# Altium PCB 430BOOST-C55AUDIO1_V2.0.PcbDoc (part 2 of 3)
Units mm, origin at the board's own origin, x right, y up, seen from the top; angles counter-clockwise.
Board outline 50.8 x 84 mm, 4 copper layers (Top Layer, GND, POW, Bottom Layer); 272 components, 169 nets, 833 pads, 607 vias.
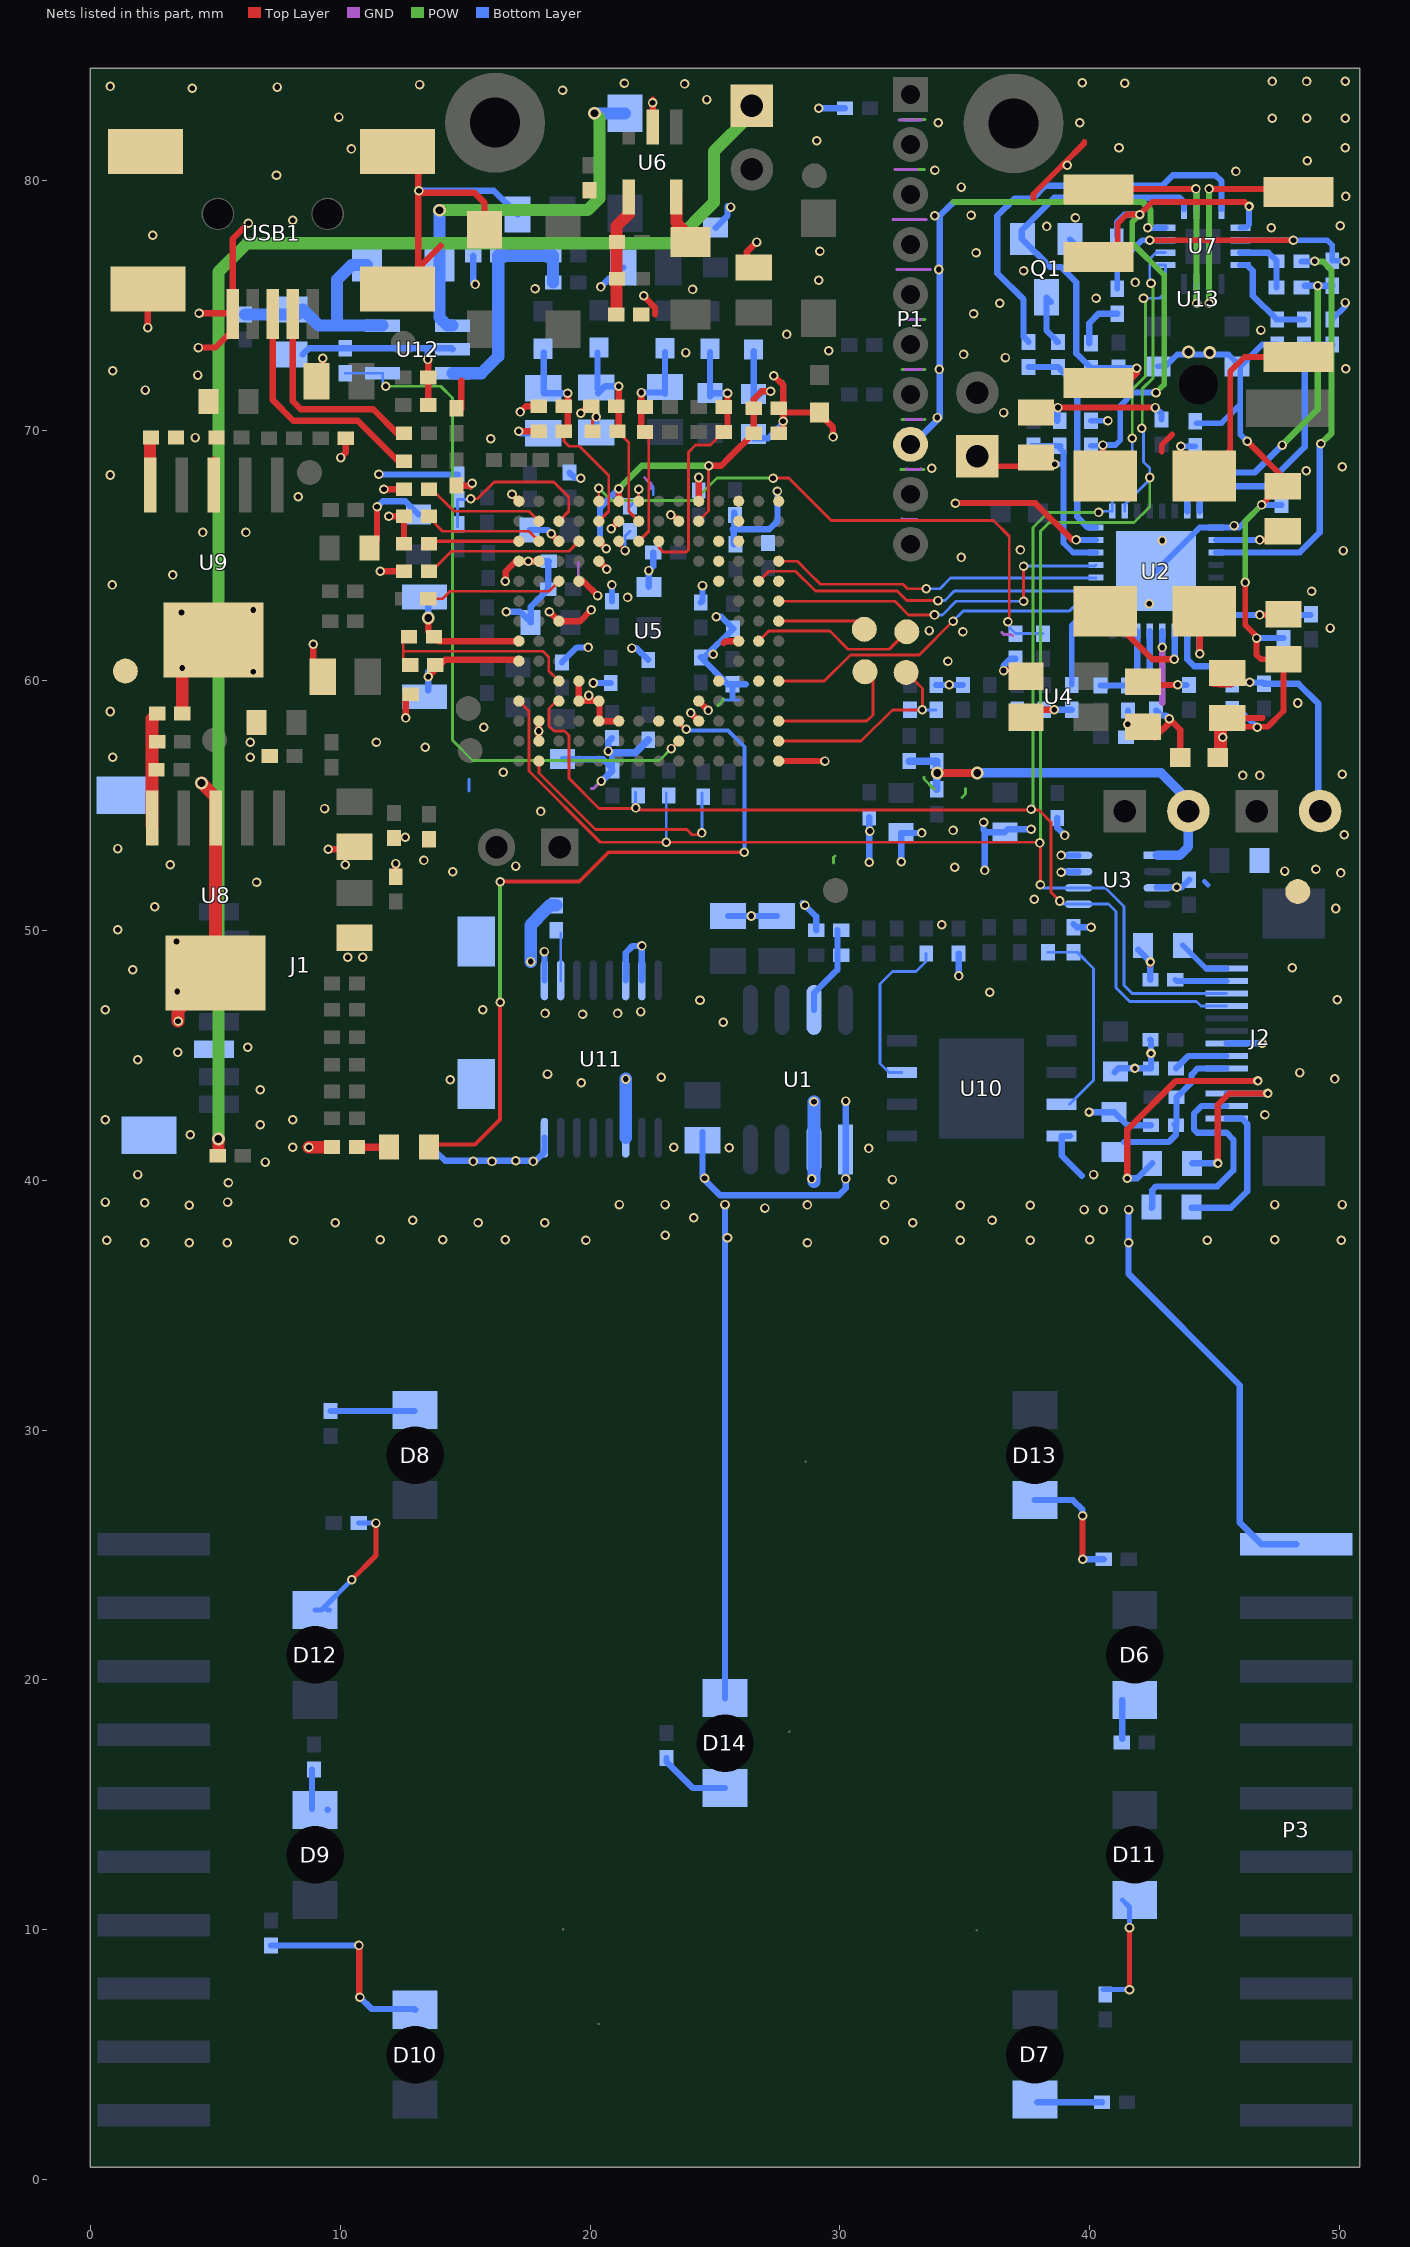
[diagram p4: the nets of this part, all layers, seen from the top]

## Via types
v1: diameter 0.381, hole 0.229, Top Layer to Bottom Layer, 549 vias
v2: diameter 0.508, hole 0.305, Top Layer to Bottom Layer, 42 vias
v3: diameter 0.381, hole 0.203, Top Layer to Bottom Layer, 16 vias

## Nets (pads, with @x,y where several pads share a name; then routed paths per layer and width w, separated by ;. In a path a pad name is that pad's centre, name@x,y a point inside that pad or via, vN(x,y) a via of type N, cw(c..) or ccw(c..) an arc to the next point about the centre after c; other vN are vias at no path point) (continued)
GND: C1.2 C4.1 C6.2 C8.1 C11.1 C14.1 C18.2 C19.1 C20.1 C21.2 C22.2 C25.1 C26.1 C27.1 C32.1 C33.1 C34.1 C35.1 C36.1 C37.1 C38.1 C39.1 C43.1 C44.1 C45.1 C46.1 C47.1 C48.1 C49.1 C50.1 C51.1 C52.1 C53.1 C54.1 C55.1 C56.2 C57.1 C58.1 C62.2 C63.1 C64.1 C65.1 C66.1 C67.1 C68.1 C73.2 C74.2 C75.1 C76.2 C77.2 C78.2 C80.1 C81.1 C82.1 C83.1 C85.2 C87.1 C88.1 C89.1 C100.2 C101.2 C102.2 C104.1 C105.2 C107.1 C108.1 C200.1 C201.1 C202.1 C203.1 C206.2 C210.1 C211.1 C220.1 D2.1 D14.2 J1.6 J1.9 J1.10 J1.11 J1.12 J2.7 L2.1 L8.1 P1.8 P3.1 R5.1 R6.1 R13.1 R16.1 R24.2 R25.1 R28.1 R29.1 R30.1 R32.1 R35.1 R40.1 R42.1 R45.2 R46.2 R47.2 R50.1 R52.1 R54.2 R56.1 R75.1 R77.2 R81.1 R82.1 R97.2 TP1.1 TP4.1 U1.1 U1.2 U2.7 U2.28 U3.3 U3.7 U3.8 U4.2 U5.A11 U5.A14 U5.B2 U5.B3 U5.B11 U5.C8 U5.C12 U5.D4 U5.D5 U5.D10 U5.E3 U5.E4 U5.E11 U5.F3 U5.F13 U5.H3 U5.J13 U5.K3 U5.K4 U5.K14 U5.L5 U5.L10 U5.M7 U5.P1 U5.P14 U6.2 U7.4 U8.3 U9.3 U10.4 U11.3 U11.8 U11.9 U11.14 U11.15 U12.2 USB1.5 USB1.6 USB1.7 USB1.8 USB1.9 | length 298.7
  Top Layer w0.114: C57.1@20.1,69.975 20.1,70.4 v1(20.25,70.55)
  Top Layer w0.25: v1(2.3,74.125) USB1.8@2.3,75.675 ; v1(4.325,73.325) 5,73.325 5.7,74.025 USB1.5@5.7,74.675 ; v1(4.35,74.7) 5.675,74.7 USB1.5@5.7,74.675 ; U9.3@4.935,67.825 U9.3@4.935,68.84 ; v1(6.325,78.305) 5.7,77.68 USB1.5@5.7,74.675 ; C21.2@8.825,71.625 C21.2@8.825,72.275 ; C21.2@8.9,71.975 C21.2@8.9,72.5 ; v1(8.925,61.45) 8.925,60.525 C85.2@9.3,60.15 ; C21.2@9.05,71.975 9.3,72.225 v1(9.3,72.9) ; v1(9.525,53.25) C62.2@10.575,53.25 ; v1(10.025,68.925) 10.225,69.125 R56.1@10.225,69.7 ; C89.1@11.175,65.3 11.475,65.6 v1(11.475,66.95) ; v1(11.6,64.375) R28.1@12.55,64.375 ; v1(11.75,67.65) R47.2@12.55,67.65 ; v1(11.95,66.575) R46.2@12.55,66.575 R45.2@12.55,65.475 ; v1@16.625,62.775 v1(16.65,62.75) ; v1(17.15,69.975) C19.1@17.95,69.975 ; v1(17.2,70.75) 17.425,70.975 C20.1@17.95,70.975 ; v1(18.45,65.875) U5.C12@18.75,65.575 ; v1(19.625,70.7) 19.9,70.975 C58.1@20.05,70.975 ; v1(19.925,61.325) v1@19.975,61.375 ; U5.E11@20.463,64.662 v1@20.7,64.425 ; U5.P1@27.55,56.775 v1(29.4,56.775) ; C44.1@27.55,70.9 27.724,70.726 L8.1@29.175,70.726 29.175,70.675 29.725,70.125 v1(29.725,69.75) ; v1(34.625,67.1) 37.825,67.1 v1@39.3,65.625 ; v1(36.55,60.4) 37.225,60.4 U4.2@37.45,60.175 ; C6.2@37.525,70.725 C6.2@37.525,71.05 ; C6.2@38.201,70.925 v1(38.725,70.925) v1(42.625,70.925) v1@42.65,70.95 ; v1(41.525,58.25) 42.075,58.25 42.6,57.725 43.175,58.3 v1(43.175,58.475) 43.626,58.024 L2.1@43.626,56.925
  Top Layer w0.254: USB1.9@0.975,80.525 1.625,81.175 USB1.9@2.2,81.175 ; C201.1@12.225,52.075 v1(12.225,52.675) ; USB1.6@12.3,75.675 USB1.6@13.125,76.5 ; USB1.7@12.3,81.175 13.125,80.35 13.125,79.6 v1@13.125,79.525 ; v1(12.625,58.5) R35.1@12.625,59.45 ; v1(13.5,72.85) 13.525,72.825 R25.1@13.525,72.125 13.525,71.575 C22.2@13.525,71.025 ; 14.025,77.4 USB1.6@13.125,76.5 ; C11.1@14.65,67.8 15.2,67.8 v1@15.225,67.775 ; C107.1@14.85,70.85 14.85,72 ; D2.1@15.775,78.05 15.775,79.125 15.375,79.525 v1@13.125,79.525 ; v1(16.601,63.978) 16.625,64.002 16.625,64.375 17.025,64.775 U5.A11@17.15,64.775 17.376,64.775 v1(17.525,64.775) U5.B11@17.95,64.775 ; U5.A14@17.15,67.175 v1@16.961,67.364 ; U5.B2@17.95,57.575 v1(17.95,57.975) U5.B3@17.95,58.375 ; v1(18.375,62.75) U5.C8@18.75,62.375 19.6,62.375 v1(20.05,62.825) ; U5.D5@19.55,59.975 U5.D4@19.55,59.175 19.557,59.182 20.001,59.182 ; U5.D10@19.55,63.975 19.725,63.975 v1(20.3,63.4) ; v1@20.001,59.324 20.001,59.182 ; v1(20.85,66.075) U5.F13@21.15,66.375 ; U5.F3@21.15,58.375 U5.E3@20.35,58.375 20.38,58.405 20.38,59.145 20.343,59.182 20.001,59.182 ; v1@22.225,75.3 22.6,74.925 22.6,74.65 ; U6.2@22.513,82.15 v1@22.513,83.237 ; v1@23.225,66.7 U5.J13@23.55,66.375 ; v1(24.025,58.7) U5.K3@24.35,58.375 ; U5.K4@24.35,59.175 v1(24.725,58.8) ; U5.K14@24.35,67.175 v1(24.35,68.125) ; 25.35,61.503 25.422,61.575 U5.M7@25.95,61.575 ; C74.2@26.275,76.525 26.275,77.15 v1(26.675,77.55) ; v1(27.35,72.2) 27.725,71.825 v1@27.725,70.553 ; C45.1@27.55,69.9 C45.1@27.657,70.007 ; C45.1@27.725,70 v1@27.725,70.553 ; v1(27.725,70.375) v1@27.725,70.553 ; v3@39.95,42.7 v3(39.975,42.725) ; v3@41.8,44.475 v3(41.802,44.475) ; v3@42.425,48.65 v3(42.425,48.741) ; v3(46.9,45.475) v3@46.925,45.45 ; USB1.6@13.125,76.5 v1@13.125,79.525 ; v1@16.961,67.364 v1(16.875,67.45) v1@16.961,67.364
  Top Layer w0.508: v1(3.51,46.365) 3.51,46.8 U8.3@5.01,48.3 U8.3@5.01,54.5 5.01,55.34 v2(4.45,55.9) ; R54.2@3.675,58.675 U9.3@3.675,60.365 ; v1(8.75,41.325) R40.1@9.575,41.325
  GND w0.114: 19.525,64.059 19.525,64.73 ; 20.064,55.673 20.142,55.673 v1(20.445,55.976) ; 22.183,68.125 22.451,67.856 22.451,67.675 ; 32.127,78.454 33.102,78.454 33.47,78.454 ; 32.2,80.45 33.075,80.45 ; 32.277,76.454 33.62,76.454 ; 32.364,82.439 33.277,82.439 ; 32.475,66.475 32.5,66.45 33.075,66.45 ; 32.584,74.45 33.255,74.45 ; 32.609,72.45 33.28,72.45 ; 32.634,70.45 33.305,70.45 ; 32.657,68.475 32.682,68.45 33.225,68.45 33.25,68.475 ; 36.475,61.925 36.554,61.846 36.859,61.846 36.927,61.778
  GND w0.254: 42.9,59.1 v1(42.9,61.325)
  POW w0.114: 25.109,58.988 25.325,59.205 25.325,59.275 ; 27.719,71.486 27.719,71.975 ; 29.749,52.702 29.749,52.924 29.801,52.976 ; 32.434,68.45 33.359,68.45 ; 32.459,78.45 33.384,78.45 ; 32.459,80.45 33.384,80.45 ; 32.484,70.45 33.409,70.45 ; 32.484,72.45 33.409,72.45 ; 32.484,74.45 33.409,74.45 ; 32.484,82.45 33.409,82.45 ; 32.509,76.45 33.434,76.45 ; 33.361,56.131 33.361,56.064 33.775,55.65 ; 34.888,55.313 35.026,55.451 35.026,55.673
  POW w0.254: v1@20.419,55.95 v1(20.445,55.976) ; 34.55,79.15 42.111,79.15 42.432,78.829 42.432,78.232 v1(42.325,78.125)
  Bottom Layer w0.114: 15.15,56.05 15.161,56.039 15.161,55.577 ; 20.064,55.673 20.142,55.673 v1(20.445,55.976) ; 22.275,68 22.501,67.774 ; 22.526,67.446 22.526,67.724 ; 25.225,59.125 25.314,59.214 25.954,59.214 ; 32.5,80.45 33.075,80.45 ; 32.525,78.45 33.1,78.45 ; 32.55,76.45 33.125,76.45 ; 32.55,82.439 33.136,82.439 ; 32.65,70.45 33.225,70.45 ; 32.65,76.45 33.225,76.45 ; 32.65,78.45 33.225,78.45 ; 32.675,74.45 33.25,74.45
  Bottom Layer w0.2: 44.6,51.95 44.725,51.825
  Bottom Layer w0.25: C102.2@8.5,73.05 8.75,73.3 R82.1@10.2,73.3 13.5,73.3 ; v1(11.475,66.95) 11.7,67.175 12.6,67.175 C82.1@13.125,66.65 ; v1(11.55,68.25) R42.1@14.7,68.25 ; v1(13.5,72.85) 13.5,73.3 ; U12.2@14.5,73.263 14.463,73.3 13.5,73.3 ; v1(16.65,62.75) 17.2,62.75 C35.1@17.625,62.325 17.625,62.95 C53.1@18.325,63.65 C33.1@18.325,64.75 ; v1(17.15,69.975) 17.225,69.9 C18.2@18.125,69.9 ; v1(17.525,64.775) C33.1@18.35,64.775 ; C37.1@17.575,66.025 18.3,66.025 v1(18.45,65.875) ; C27.1@18.875,60.725 19.475,61.325 v1(19.925,61.325) ; C32.1@19.175,68.325 19.4,68.1 v1(19.625,68.1) ; C56.2@20.25,69.925 v1(20.25,70.55) v1@20.25,70.7 ; v1(20.425,75.75) 21.2,76.525 C105.2@21.325,76.525 ; C55.1@20.875,63.175 v1(20.875,63.825) ; C54.1@22.35,63.75 v1(22.35,64.4) 22.525,64.575 C48.1@22.525,65.125 ; D14.2@25.4,19.27 25.4,21.5 ; 25.4,20.54 25.4,21.5 ; 25.4,35.375 25.4,33.2 ; v1(25.4,39.025) 25.4,33.2 ; C77.2@25.525,50.575 v1(26.45,50.575) C78.2@27.475,50.575 ; C43.1@26.55,69.7 27.125,69.7 27.625,70.2 ; v1@28.5,51.1 29.05,50.55 R52.1@29.05,50 ; v1(29.15,82.9) R6.1@30.2,82.9 ; v1(31.175,52.725) C50.1@31.175,54.525 ; v1(32.45,52.75) C39.1@32.45,53.9 v1(33.275,53.9) ; R97.2@33.85,59.825 v1(34.375,59.825) R32.1@34.925,59.825 ; v1(35.75,54.325) 35.75,54.025 35.85,53.925 ; v1(35.8,52.4) 35.8,53.875 35.85,53.925 ; v1(36.55,60.4) 36.55,60.6 36.825,60.875 R29.1@37.025,60.875 ; v1(37.65,54.05) 36.725,54.05 C52.1@36.6,53.925 ; C34.1@38.7,54.5 38.7,54.1 v1(39,53.8) ; C8.1@38.7,70.4 v1@38.7,70.925 ; v1@38.825,52.35 U3.7@39.55,52.35 ; v1@38.825,53 U3.8@39.55,53 ; R75.1@39.35,50.25 39.475,50.125 v1(40.05,50.125) ; C14.1@41.525,57.8 v1(41.525,58.25) R24.2@41.525,58.8 ; v1(42.625,70.925) 42.875,70.675 R16.1@42.875,70.45 ; C4.1@42.65,58.8 42.85,58.6 43.05,58.6 v1(43.175,58.475) ; U3.3@42.675,51.725 v1@43.45,51.725 ; 25.4,21.5 25.4,33.2 ; 35.85,53.925 C52.1@36.6,53.925 ; 35.85,53.925 C52.1@36.6,53.925
  Bottom Layer w0.254: v1(13.15,79.6) 16.15,79.6 C73.2@17.1,78.65 ; 13.85,41.125 14.2,40.775 v1(17.025,40.775) 17.825,40.775 18.175,41.125 U11.8@18.175,41.7 18.175,41.175 U11.8@18.125,41.125 ; R81.1@15.325,77 15.325,75.925 v1(15.4,75.85) ; U11.9@18.175,48 v1(18.175,49.15) ; C26.1@18.9,56.85 20.525,56.85 20.875,56.5 20.875,57.025 v1@20.8,57.1 ; v1(20.125,59.9) C63.1@20.825,59.9 ; v1(20.445,55.976) 20.476,55.976 R5.1@20.9,56.4 ; v1(20.725,57.175) 20.725,57.55 C65.1@20.875,57.7 ; U11.14@21.425,48 21.425,49.1 21.7,49.375 v1(22.075,49.375) U11.15@22.075,48 ; v1(21.675,61.3) 21.85,61.3 C49.1@22.325,60.825 ; C25.1@24.425,63.125 24.5,63.2 v1(24.5,63.8) ; C76.2@24.5,41.925 24.5,40.1 25.2,39.4 25.4,39.4 29.95,39.4 30.23,39.68 U1.1@30.23,41.231 ; C104.1@25.025,78.125 25.5,78.6 v1@25.5,78.975 ; v1(25.05,62.55) 25.25,62.55 C47.1@25.725,62.075 24.575,60.925 C67.1@24.425,60.925 25.5,59.85 C46.1@25.7,59.85 ; 25.7,59.35 C46.1@25.7,59.85 ; 25.7,66.053 26.226,66.053 27.178,66.053 27.5,66.375 v1(27.5,67.575) ; C66.1@25.75,65.447 25.75,66.05 ; 25.775,66.05 C68.1@25.775,66.722 ; 26.229,59.85 C46.1@25.7,59.85 ; v1@30.23,39.95 U1.1@30.23,41.231 ; v1(30.23,43.17) U1.1@30.23,41.231 ; P1.8@32.925,69.45 34,70.525 34,78.6 34.303,78.903 34.55,79.15 ; v1(34.75,48.175) C200.1@34.75,49.075 ; U10.4@39.205,41.77 U10.4@38.875,41.77 38.875,40.975 39.675,40.175 ; v1@39.575,65.625 U2.7@40.25,65.625 ; v3(39.975,42.725) C203.1@40.975,42.725 41.5,42.2 C202.1@42.45,42.2 ; C211.1@41,44.325 C211.1@41.025,44.35 41.15,44.475 v3(41.802,44.475) C220.1@42.45,44.475 v3(42.45,45.077) 42.45,45.6 C210.1@42.425,45.625 ; v1(41.55,38.825) 41.55,38.525 41.55,38.3 41.55,36.25 46,31.8 46,26.3 46.87,25.43 P3.1@48.26,25.43 ; C100.2@41.945,49.22 v3(42.425,48.741) R77.2@42.425,48.025 ; v1(42.325,78.125) U7.4@43.025,78.125 ; v1(42.9,61.325) U2.28@42.9,61.975 ; v1@43.45,51.725 43.675,51.725 C108.1@43.975,52.025 ; J2.7@45.475,45.475 v3(46.9,45.475)
  Bottom Layer w0.3: v1(20.725,57.175) 20.8,57.1 21.8,57.1 C38.1@22.325,57.625
  Bottom Layer w0.508: v1(17.625,48.75) 17.625,50.21 17.884,50.469 17.884,50.5 18.384,51 R13.1@18.65,51 ; U11.3@21.425,41.7 v1(21.425,44.05) ; v1@28.96,39.94 U1.2@28.96,41.231 v1(28.96,43.135)
  other v1: 2.18,37.5 3.958,37.5 5.482,37.5 28.7,37.5 41.55,37.5 0.656,37.6 8.149,37.6 19.833,37.6 31.771,37.6 34.819,37.6 37.613,37.6 44.7,37.6 50.059,37.6 11.6,37.615 14.1,37.615 16.6,37.615 40,37.615 47.4,37.615 25.5,37.7 23.008,37.8 9.8,38.3 15.515,38.3 18.182,38.3 32.914,38.3 12.9,38.4 36.089,38.4 24.151,38.5 39.772,38.825 40.534,38.825 27,38.885 3.958,39 28.7,39.012 31.8,39.012 34.819,39 37.613,39 21.175,39.025 23,39.025 47.4,39.025 50.1,39.025 2.18,39.1 0.6,39.125 5.489,39.125 5.525,39.9 32.1,40.028 28.875,40.05 30.225,40.05 24.583,40.075 1.9,40.225 40.153,40.225 7,40.725 15.325,40.75 16.075,40.75 17.725,40.75 31.15,41.272 25.575,41.3 8.1,41.325 23.35,41.325 4,41.825 6.8,42.225 0.6,42.425 8.1,42.425 47.011,42.625 6.8,43.625 19.65,43.9 14.4,44.025 49.8,44.053 22.85,44.125 18.296,44.25 48.4,44.307 1.9,44.825 3.5,45.125 6.3,45.325 25.325,46.325 19.7,46.644 18.2,46.675 21.1,46.675 22.025,46.75 0.6,46.825 15.7,46.825 24.4,47.2 49.9,47.228 36,47.525 3.475,47.55 1.7,48.425 48.1,48.498 10.3,48.925 10.9,48.925 3.45,49.55 1.1,50.025 34.075,50.225 49.843,50.875 2.575,50.95 28.6,51 37.775,51.25 43.475,51.725 6.65,51.925 50.05,52.3 38.85,52.325 14.5,52.35 47.8,52.375 49.05,52.45 34.6,52.525 17.025,52.575 3.2,52.625 10.2,52.625 13.35,52.8 38.85,53 1.1,53.275 12.6,53.725 50.186,53.825 31.2,53.975 34.527,54 18.025,54.759 9.375,54.873 16.525,56.325 0.9,56.925 6.4,56.925 13.4,57.325 6.4,57.525 11.45,57.525 15.75,58.125 0.8,58.76 19.95,59.4 6.525,60.35 3.675,60.5 34.325,60.775 24.925,61.05 34.925,61.95 33.575,62 3.65,62.725 6.525,62.825 21.5,63.325 0.875,63.825 3.3,64.225 20.668,64.457 34.85,64.925 37.225,65.225 39.45,65.625 4.5,65.925 6.225,65.925 23.225,66.625 8.325,67.35 15.275,67.9 0.8,68.225 33.675,68.5 16.025,69.675 4.2,69.725 33.9,70.525 36.55,70.725 2.2,71.625 4.3,72.225 0.9,72.4 33.975,72.45 34.95,73.05 23.825,73.125 29.55,73.2 27.875,73.85 35.35,74.675 22.15,75.4 24.1,75.65 17.8,75.675 29.15,76.025 33.95,76.45 35.45,77.125 29.2,77.175 2.5,77.825 8.1,78.419 33.8,78.597 35.25,78.625 25.625,78.95 34.85,79.75 7.45,80.225 33.803,80.425 10.45,81.275 29.075,81.6 33.93,82.325 9.95,82.55 22.5,83.125 24.675,83.25 18.9,83.625 4.075,83.7 4.075,83.7 4.075,83.7 4.075,83.7 7.475,83.75 0.8,83.775 13.175,83.85 23.783,83.875 21.375,83.9
GND-AIC: C2.2 C3.1 C5.1 C7.2 C9.1 C16.2 C17.1 C106.1 C109.1 C110.1 C111.1 L2.2 Q1.2 R9.1 R10.1 R14.1 R93.1 U2.17 U2.33 U7.3 U7.10 | length 60.9
  Top Layer w0.229: 37.75,79.3 37.75,79.475 38.89,80.615 ; v1@38.975,80.7 38.89,80.615 ; 39.775,81.55 39.775,81.5 38.89,80.615 ; v1(42.402,77.625) v1(48.15,77.625) ; 42.875,69.15 42.875,69.425 43.3,69.85 ; C7.2@45.124,58.124 C7.2@45.5,58.5 46.925,58.5 ; C7.2@45.35,58.4 45.35,58.325 C7.2@45.45,58.425 ; C7.2@45.5,58.15 v1@46.7,58.15 ; v1(46.225,63.925) 46.225,62.225 v1@46.675,61.775 ; v1(46.3,69.575) 47.725,68.15 C16.2@47.725,67.775 47.625,67.775 v1(46.875,67.025) ; v1(46.675,61.7) 46.675,61.025 46.85,60.85 C2.2@47.75,60.85 ; v1(46.7,58.125) v1@46.7,58.15 ; C2.2@47.75,60.675 C2.2@47.75,60.85 ; v1@46.7,58.15 47.125,58.15 47.75,58.775 C2.2@47.75,60.85
  Top Layer w0.508: L2.2@45.124,56.925 45.231,57.031 C7.2@45.231,58.769
  POW w0.229: v1(46.225,63.925) 46.225,66.375 v1(46.875,67.025)
  Bottom Layer w0.229: Q1.2@39.203,77.666 40.093,76.775 R93.1@41.075,76.775 ; R9.1@40.05,70.4 v1(40.725,70.4) ; C111.1@41.1,75.675 41.1,76.625 42.1,77.625 v1(42.402,77.625) U7.3@43.025,77.625 ; U2.33@42.65,64.375 44.4,66.125 U2.17@45.05,66.125 45.975,66.125 v1(46.875,67.025) C17.1@47.675,67.025 ; C110.1@42.725,72.575 43.025,72.575 43.5,73.05 45.55,73.05 C109.1@46.025,72.575 ; R10.1@44.275,70.3 45.275,70.3 46.025,71.05 ; C9.1@45.7,58.85 45.975,58.85 v1(46.7,58.125) ; U7.10@46.025,77.625 49.5,77.625 49.7,77.425 C106.1@49.7,76.8 v1@50.125,76.8 ; v1(46.3,69.575) 46.025,69.85 46.025,71.05 ; v1(46.675,61.7) C5.1@47.75,61.7 ; R14.1@47.5,73.45 46.9,73.45 C109.1@46.025,72.575 ; C3.1@49.7,74.45 50.225,74.975 v1(50.225,75.125) ; 46.025,71.05 C109.1@46.025,72.575
  other v1: 46.125,56.2 46.8,56.2 50.1,56.245 45.325,57.725 48.325,59.1 49.625,62.1 42.375,63.075 48.875,63.575 50.15,65.2 42.9,65.6 45.775,66.2 48.662,68.4 50.1,68.55 50.25,72.475 36.625,72.925 46.85,74.025 36.4,75.1 40.25,75.3 41.825,75.93 37.35,76.4 50.225,76.775 47.265,78.125 38.275,78.175 50.025,78.2 39.425,78.525 50.25,79.375 45.85,80.375 39.1,80.625 48.7,80.8 41.169,81.325 50.225,81.325 39.6,82.325 47.3,82.5 48.689,82.5 50.225,82.5 41.4,83.9 39.7,83.925 47.3,83.975 48.675,83.975 50.225,83.981
  other v2: 44.8,73.125 43.95,73.15
GPIO10: U5.L12
GPIO11: U5.M12
GPIO12: R82.2 U5.J2 U12.4 | length 29
  Top Layer w0.114: v1(23.25,57.275) U5.J2@23.55,57.575
  POW w0.114: v1(11.826,71.778) 11.829,71.775 14.025,71.775 14.488,71.312 14.488,57.612 15.3,56.8 22.775,56.8 v1(23.25,57.275)
  Bottom Layer w0.114: R82.2@10.202,72.298 U12.4@11.7,72.298 ; U12.4@11.023,72.298 U12.4@11.7,72.298 ; v1(11.826,71.778) 11.7,71.904 U12.4@11.7,72.298
GPIO13: U5.N5
GPIO14: R96.1 R97.1 TP7.1 U5.P2 | length 9.1
  Top Layer w0.114: U5.P2@27.55,57.575 30.85,57.575 32.1,58.825 v1(33.3,58.825) 33.3,59.675 TP7.1@32.65,60.325
  Bottom Layer w0.114: R96.1@32.8,58.825 v1(33.3,58.825) R97.1@33.85,58.825
GPIO15: TP10.1 U5.N7 | length 6.7
  Top Layer w0.114: U5.N7@26.75,61.575 27.15,61.975 29.6,61.975 30.325,61.25 31.975,61.25 TP10.1@32.675,61.95
GPIO16: TP11.1 U5.P3 | length 5.7
  Top Layer w0.114: U5.P3@27.55,58.375 31.075,58.375 31.325,58.625 31.325,60.025 TP11.1@31,60.35
GPIO17: TP12.1 U5.P8 | length 3.5
  Top Layer w0.114: U5.P8@27.55,62.375 28.951,62.375 29.65,62.375 TP12.1@31.025,62.375
HP_LEFT: C13.2 R10.2 U13.4 | length 9.7
  Top Layer w0.229: v1(43.65,69.375) 43.65,68.68 C13.2@44.225,68.105 ; C13.2@44.575,68.18 45.625,69.23 45.625,72.375 46.2,72.95 U13.4@48.35,72.95
  Bottom Layer w0.229: v1(43.65,69.375) R10.2@44.225,69.375
HP_RIGHT: C15.2 R9.2 R93.2 U7.9 U13.3 | length 24
  Top Layer w0.229: C15.2@40.1,68.325 40.345,68.08 C15.2@40.45,68.08 ; U13.3@40.35,76.95 40.675,76.95 41.125,77.4 41.125,78.3 41.475,78.65 v3(42,78.65) 42.5,79.15 46.2,79.15 v3(46.375,78.975) ; C15.2@40.525,68.35 v1(40.525,69.425)
  POW w0.229: v3(42,78.65) 41.7,78.35 41.7,77.5 42.975,76.225 42.975,71.85 v1(42.65,71.525)
  Bottom Layer w0.229: R9.2@40.05,69.4 v1@40.525,69.4 ; v1(40.525,69.425) 41.025,69.425 41.225,69.625 41.225,71 41.75,71.525 v1(42.65,71.525) ; R93.2@41.075,77.775 41.075,78.35 41.375,78.65 v3(42,78.65) ; U7.9@46.025,78.125 46.25,78.125 46.375,78.25 v3(46.375,78.975)
I2C_SCL: J2.10 R38.1 U2.9 U3.5 U5.C4 U7.1 | length 64.3
  Top Layer w0.114: U5.C4@18.75,59.175 18.65,59.175 18.354,58.879 18.354,58.171 18.55,57.975 18.975,57.975 19.15,57.8 19.15,56.088 20.363,54.875 v1@21.8,54.875 ; v1@21.825,54.875 v1@21.8,54.875 ; v1@38.787,51.187 38.45,51.525 38.45,54.325 37.962,54.813 21.862,54.813 v1@21.8,54.875 ; v1@42.125,75.325 v1(42.15,75.3)
  POW w0.114: v1@37.55,54.825 37.725,55 37.725,66.125 38.325,66.725 39.902,66.725 v1(40.35,66.725) ; v1(41.7,69.7) 41.7,71.65 42.237,72.187 42.237,75.213 v1(42.15,75.3)
  Bottom Layer w0.114: v1@21.825,54.95 R38.1@21.825,55.525 ; v1(38.8,51.175) 38.925,51.05 U3.5@39.55,51.05 40.75,51.05 41.05,50.75 41.05,47.7 41.6,47.15 44.275,47.15 44.45,46.975 J2.10@45.475,46.975 ; v1(40.35,66.725) 40.4,66.775 U2.9@40.9,66.775 40.9,67.3 41.7,68.1 v1(41.7,69.7) ; v1(42.15,75.3) 42.8,75.3 43.025,75.525 U7.1@43.025,76.625 U7.1@42.75,76.625
  other v1: 37.65,54.85 21.825,54.9
I2C_SDA: J2.11 R39.1 U2.10 U3.6 U5.A4 U7.2 | length 69.8
  Top Layer w0.114: U5.A4@17.15,59.175 17.554,58.771 17.554,56.377 20.405,53.525 v1(23.05,53.525) v1@37.9,53.525 ; v1@38.025,51.875 v1@38.025,53.55 ; v1(42.077,70.098) v1@42.1,70.121
  POW w0.114: v1@37.925,53.5 38.025,53.6 38.025,65.975 38.375,66.325 41.05,66.325 ; 41.375,66.325 41.05,66.325 ; v1@42.1,70.098 42.1,71.675 42.525,72.1 v1@42.525,75.9 ; v1(42.4,68.125) 42.4,66.95 41.775,66.325 41.05,66.325
  Bottom Layer w0.114: v1(23.05,53.525) R39.1@23.05,55.5 ; v1@37.925,51.825 v1(38.025,51.825) 38.15,51.7 U3.6@39.55,51.7 40.625,51.7 41.375,50.95 41.375,47.8 41.7,47.475 J2.11@45.475,47.475 ; U2.10@41.4,66.775 41.4,67.05 v1@42.425,68.075 ; v1(42.077,70.098) 42.15,70.025 42.15,68.75 42.4,68.5 v1(42.4,68.125) ; v1@42.387,68.113 v1@42.425,68.075 ; v1@42.425,68.125 v1@42.425,68.075 ; v1@42.525,75.9 42.4,76.025 42.4,76.875 42.65,77.125 U7.2@43.025,77.125
  other v1: 38,53.5 42.45,75.9
I2S1_CLK: U5.M14
I2S1_DX: U5.M13
I2S1_FS: U5.L11
I2S1_RX: U5.P10
I2S2_CLK: U2.2 U5.P5 | length 14
  Top Layer w0.114: U5.P5@27.55,59.975 29.375,59.975 30.421,61.021 33.046,61.021 33.173,61.021 v1(34.527,62.375)
  Bottom Layer w0.114: v1(34.527,62.375) 34.927,62.775 39.175,62.775 39.525,63.125 U2.2@40.25,63.125
I2S2_DX: U2.4 U5.P11 | length 13.3
  Top Layer w0.114: U5.P11@27.55,64.775 28.3,64.775 28.788,64.287 29.225,63.85 32.525,63.85 32.7,63.675 v1(33.45,63.675)
  Bottom Layer w0.114: v1(33.45,63.675) 34,63.675 34.425,64.1 U2.4@40.25,64.1
I2S2_FS: U2.3 U5.N10 | length 14.3
  Top Layer w0.114: U5.N10@26.75,63.975 26.757,63.975 27.154,64.371 28.229,64.371 29.021,63.579 32.296,63.579 32.675,63.2 v1(33.925,63.2)
  Bottom Layer w0.114: v1(33.925,63.2) 34.2,63.2 34.579,63.579 40.204,63.579 U2.3@40.25,63.625
I2S2_RX: U2.5 U5.P9 | length 14.8
  Top Layer w0.114: U5.P9@27.55,63.175 32.2,63.175 32.75,62.625 v1(33.775,62.625) ; v1(37.35,63.175) v1@37.35,64.529
  POW w0.114: v1(33.775,62.625) v1(33.8,62.625)
  Bottom Layer w0.114: v1(33.8,62.625) 34.1,62.625 34.65,63.175 36.952,63.175 ; 37.15,63.175 36.952,63.175 ; v1@37.325,64.579 40.204,64.579 U2.5@40.25,64.625 ; v1(37.35,63.175) 36.952,63.175
  other v1: 37.35,64.575
MCLK: R19.1 U2.1 | length 3.5
  Bottom Layer w0.229: R19.1@39.275,59.825 39.275,62.2 39.7,62.625 U2.1@40.25,62.625
MIC_DET: R94.2 R95.2 U2.8 | length 8.4
  Bottom Layer w0.25: R94.2@37.55,72.55 R95.2@38.725,72.55 39.5,71.775 39.5,66.55 39.925,66.125 U2.8@40.25,66.125
MICN: C12.2 R14.2 U7.12 | length 4
  Bottom Layer w0.25: U7.12@46.025,76.625 46.3,76.625 46.525,76.4 46.525,75.4 47.475,74.45 R14.2@47.5,74.45 C12.2@48.575,74.45
MICP: C10.2 R12.1 U7.11 | length 2.7
  Bottom Layer w0.25: U7.11@46.025,77.125 47.15,77.125 47.475,76.8 R12.1@47.475,76.775 C10.2@47.475,75.725
NetC1_1: C1.1 C4.2 R1.2 U2.29 | length 4.5
  Top Layer w0.25: 42.9,59.825 v1(43.525,59.825)
  Bottom Layer w0.25: U2.29@42.4,61.975 42.4,60.075 C4.2@42.65,59.825 v1(43.525,59.825) ; v1@43.425,59.825 v1(43.525,59.825) ; R1.2@43.775,59.825 v1(43.525,59.825) ; R1.2@43.875,59.825 v1(43.525,59.825)
NetC2_1: C2.1 C5.2 R2.1 U2.24 | length 5
  Top Layer w0.25: v1(46.8,62.625) C2.1@47.725,62.625
  Bottom Layer w0.25: U2.24@45.05,62.625 v1(46.8,62.625) 47.402,62.625 ; C5.2@47.675,62.625 47.402,62.625 ; R2.1@48.825,62.625 47.402,62.625
NetC3_2: C3.2 C12.1 U2.16 | length 10.9
  Bottom Layer w0.25: U2.16@44.4,66.775 44.4,67.45 44.725,67.775 47.025,67.775 48.6,69.35 C12.1@48.6,73.425 ; C12.1@48.575,73.45 C3.2@49.7,73.45
NetC6_1: C6.1 C8.2 JP1.1 R3.2 U2.6 | length 10.7
  Top Layer w0.229: JP1.1@35.25,68.98 35.678,68.553 35.7,68.575 37.175,68.575 37.525,68.925 37.8,68.65 C6.1@38.45,68.65
  Bottom Layer w0.229: R3.2@37.675,69.4 C8.2@38.825,69.4 ; v1@38.45,68.65 38.928,68.65 ; C8.2@38.7,69.4 38.95,69.15 38.95,65.5 39.325,65.125 U2.6@40.25,65.125
  other v1: 38.6,68.65
NetC7_1: C7.1 C9.2 JP2.2 R4.1 U2.26 | length 12
  Top Layer w0.25: C7.1@44.95,59.875 45.15,59.875 45.175,59.85 C7.1@45.675,59.85
  Bottom Layer w0.25: U2.26@43.9,61.975 43.9,60.85 44.175,60.575 45.575,60.575 45.675,60.475 45.675,59.85 C9.2@45.7,59.85 45.775,59.925 v1(46.4,59.925) 46.925,59.925 R4.1@46.975,59.875 R4.1@47.025,59.875 ; R4.1@47,59.9 R4.1@47.025,59.875 ; JP2.2@49.145,55.35 49.145,58.25 49.145,59.08 48.35,59.875 R4.1@47.025,59.875
NetC10_1: C10.1 C106.2 U2.15 | length 13.6
  POW w0.25: v1(47.7,69.425) 49.125,70.85 v1(49.125,75.8)
  Bottom Layer w0.25: U2.15@43.9,66.775 43.9,67.403 43.9,67.8 44.425,68.325 44.827,68.325 45.977,68.325 46.6,68.325 v1(47.7,69.425) ; C10.1@48.6,75.8 C106.2@49.7,75.8
NetC13_1: C13.1 U2.25 | length 2.2
  Top Layer w0.25: C13.1@44.225,62.295 44.4,62.12 v1@44.4,61.05
  Bottom Layer w0.25: v1(44.4,61.075) U2.25@44.4,61.975
NetC15_1: C15.1 U2.27 | length 5
  Top Layer w0.25: C15.1@40.68,62.67 42.5,60.85 43.077,60.85 ; 42.7,60.85 43.077,60.85 ; v1(43.375,60.85) 43.077,60.85
  Bottom Layer w0.25: v1@43.4,60.85 U2.27@43.4,61.975
NetC16_1: C16.1 C17.2 U2.18 | length 3.9
  Top Layer w0.25: v1(46.8,65.625) 47.375,65.625 C16.1@47.725,65.975
  Bottom Layer w0.25: U2.18@45.05,65.625 v1(46.8,65.625) 47.275,65.625 C17.2@47.675,66.025
NetC18_1: C18.1 C19.2 C20.2 L3.2 U5.E13 | length 8.8
  Top Layer w0.114: C19.2@18.95,69.975 18.95,69.575 19.15,69.375 19.575,69.375 20.75,68.2 20.75,66.775 U5.E13@20.35,66.375
  Top Layer w0.254: C19.2@19.1,70.05 19.1,70.628 19.1,70.975 v1(19.1,71.5)
  Bottom Layer w0.254: L3.2@18.15,73.126 18.15,71.5 v1(19.1,71.5)
NetC23_1: C23.1 C24.1 U5.C5 | length 8.3
  Top Layer w0.114: C24.1@12.525,60.75 C23.1@12.525,61.95 ; 12.529,61.171 18.114,61.171 18.346,60.939 18.346,60.379 U5.C5@18.75,59.975 U5.C5@18.743,59.975
NetC23_2: C23.2 U5.A7 Y1.2 | length 5.1
  Top Layer w0.249: v2(13.525,62.5) 13.525,61.975 C23.2@13.75,61.75 13.93,61.57 17.145,61.57 U5.A7@17.15,61.575
  Bottom Layer w0.249: v2(13.525,62.5) Y1.2@13.525,63.3
NetC24_2: C24.2 U5.A6 Y1.1 | length 6.3
  Top Layer w0.114: 15.55,60.775 U5.A6@17.15,60.775
  Top Layer w0.254: v1(13.525,60.15) 14.207,60.832 17.093,60.832 U5.A6@17.15,60.775
  Bottom Layer w0.254: Y1.1@13.525,59.6 v1(13.525,60.15) 13.525,60.35
NetC29_1: C29.1 C30.2 C31.2 L4.2 U5.G12 | length 8.8
  Top Layer w0.114: U5.G12@21.95,65.575 22.35,65.975 22.35,69.75 C31.2@22.2,69.9
  Top Layer w0.254: v1(22.05,71.525) 22.05,70.05 C31.2@22.2,69.9
  POW w0.254: v1(22.05,71.525) v1@22.075,71.525
  Bottom Layer w0.254: v1(22.05,71.525) C29.1@22.95,71.525 ; C29.1@23,71.475 L4.2@23,73.151
NetC40_2: C40.2 C41.2 C42.2 L5.2 U5.H12 | length 11.2
  Top Layer w0.114: U5.H12@22.75,65.575 22.75,65.325 22.925,65.15 23.85,65.15 23.946,65.246 23.946,67.603 23.946,69.146 24.225,69.425 24.825,69.425 C41.2@25.35,69.95
  Top Layer w0.254: C41.2@25.5,70.025 v1(25.5,71.5)
  Bottom Layer w0.254: L5.2@24.8,73.151 24.8,71.375 24.925,71.5 v1(25.5,71.5)
NetC43_2: C43.2 C44.2 C45.2 L6.2 U5.E12 U5.F14 U5.K13 | length 17.7
  Top Layer w0.114: U5.K13@24.35,66.375 24.35,66.382 24.746,66.779 v1(24.746,68.6)
  Top Layer w0.254: U5.E12@20.35,65.575 v1(20.65,65.275) ; U5.F14@21.15,67.175 v1(21.15,67.675) ; v1(24.746,68.6) 25.25,68.6 25.575,68.925 C45.2@26.55,69.9 C44.2@26.55,70.9 26.55,70.925 26.55,71.25 26.875,71.575 v1(27.225,71.575)
  POW w0.254: v1(21.15,67.675) 22.075,68.6 24.351,68.6 v1(24.746,68.6)
  Bottom Layer w0.254: v1(20.65,65.275) 20.4,65.525 20.4,66.925 v1(21.15,67.675) ; L6.2@26.55,73.176 C43.2@26.55,71.3 ; C43.2@26.825,71.575 C43.2@26.55,71.3 ; v1(27.225,71.575) 26.9,71.575 26.625,71.3 C43.2@26.55,71.3
NetC56_1: C56.1 C57.2 C58.2 L7.2 U5.G13 | length 8
  Top Layer w0.114: C58.2@20.875,70.95 C58.2@20.9,70.925 ; C57.2@21.1,69.975 21.55,69.525 21.55,66.775 U5.G13@21.95,66.375
  Top Layer w0.254: C57.2@21.15,70.125 v1(21.15,71.775)
  Bottom Layer w0.254: C56.1@20.3,71.674 L7.2@20.3,73.125 ; C56.1@20.325,71.5 20.6,71.775 v1(21.15,71.775)
NetC71_2: C71.2 U5.C10 | length 5.5
  Top Layer w0.114: C71.2@13.525,63.275 14.1,63.275 14.4,63.575 18.35,63.575 U5.C10@18.75,63.975
NetC72_1: C72.1 R49.1 R50.2 U6.4 | length 4.9
  Top Layer w0.483: R50.2@21.05,74.65 21.05,78.175 21.548,78.672 U6.4@21.548,79.35
NetC79_1: C79.1 R20.1 R54.1 U8.5 | length 4.6
  Top Layer w0.508: U8.5@2.47,54.2 2.47,58.47 R54.1@2.675,58.675
NetC83_2: C83.2 U9.5 | length 1.8
  Top Layer w0.483: U9.5@2.395,67.825 C83.2@2.395,69.67
NetC100_1: C100.1 J2.13 | length 2.1
  Bottom Layer w0.229: C100.1@43.725,49.4 44.65,48.475 J2.13@45.475,48.475
NetC102_1: C102.1 L11.1 R79.2 U12.5 | length 9.4
  Bottom Layer w0.483: R79.2@6.2,74.65 7.025,74.65 ; 6.725,74.65 7.025,74.65 ; 9.875,74.225 9.875,76.05 10.45,76.625 L11.1@11.075,76.625 ; U12.5@11.7,74.203 9.148,74.203 8.5,74.85 8.3,74.65 7.025,74.65
NetC103_1: C103.1 R80.1 R81.2 U12.3 | length 9.4
  Bottom Layer w0.483: U12.3@14.5,72.298 15.648,72.298 16.325,72.975 R81.2@16.325,77 C103.1@18.525,77 R80.1@18.525,75.925
NetC111_2: C111.2 R92.1 | length 2.1
  Bottom Layer w0.25: R92.1@39.975,73.5 39.975,74.3 40.35,74.675 C111.2@41.1,74.675
NetC202_2: C202.2 C203.2 J2.5 R76.1 | length 6.5
  Bottom Layer w0.25: 41.375,41.525 43.15,41.525 43.45,41.825 C202.2@43.45,42.175 ; C202.2@43.4,42.225 C202.2@43.45,42.175 ; C202.2@43.45,42.2 C202.2@43.45,42.175 ; J2.5@45.475,44.475 44.325,44.475 44.075,44.225 44.075,43.925 R76.1@43.475,43.325 43.475,42.2 C202.2@43.45,42.175
NetC208_1: C208.1 J2.2 | length 9.3
  Bottom Layer w0.25: C208.1@42.475,38.9 42.5,38.925 42.5,39.6 42.65,39.75 45.1,39.75 45.75,40.4 45.75,40.977 45.75,41.625 45.475,41.9 44.3,41.9 44.175,42.025 44.175,42.675 44.475,42.975 J2.2@45.475,42.975
NetC208_2: C208.2 J2.1 | length 6.1
  Bottom Layer w0.25: C208.2@44.075,38.9 45.65,38.9 46.3,39.55 46.3,42.25 46.075,42.475 J2.1@45.475,42.475
NetC209_1: C209.1 J2.4 | length 10.5
  Top Layer w0.25: v3(41.5,40.075) 41.5,42.025 43.45,43.975 v3(46.725,43.975)
  Bottom Layer w0.25: v3(41.5,40.075) 41.9,40.075 C209.1@42.5,40.675 ; J2.4@45.475,43.975 v3(46.725,43.975)
NetC209_2: C209.2 J2.3 | length 7.2
  Top Layer w0.25: v3(45.125,40.675) 45.125,43.025 45.575,43.475 v3(47.125,43.475)
  Bottom Layer w0.25: C209.2@44.1,40.675 v3(45.125,40.675) ; J2.3@45.475,43.475 v3(47.125,43.475)
NetC220_2: C220.2 J2.6 | length 2.2
  Bottom Layer w0.25: C220.2@43.45,44.475 43.95,44.975 J2.6@45.475,44.975
NetD3_1: D3.1 U5.J3 | length 33.5
  Top Layer w0.152: D3.1@13.55,41.325 13.65,41.425 15.4,41.425 16.4,42.425 v1(16.4,47.125) ; v1(16.4,51.95) 19.565,51.95 20.74,53.125 22.676,53.125 ; U5.J3@23.55,58.375 23.55,58.305 23.803,58.053 v1(23.851,58.053) ; 25.3,53.125 22.676,53.125 ; v1(26.175,53.125) 22.676,53.125
  POW w0.152: v1(16.4,47.125) v1(16.4,51.95) v1@16.4,52.025
  Bottom Layer w0.152: v1(23.851,58.053) 23.904,58 24.401,58 ; 24.05,58 24.401,58 ; v1(26.175,53.125) 26.175,57.35 25.525,58 24.401,58
NetD3_2: D3.2 R40.2 | length 1.4
  Top Layer w0.305: R40.2@10.575,41.325 D3.2@11.95,41.325
NetD5_1: D5.1 L11.2 U12.1 | length 16.3
  POW w0.483: v2(13.975,78.825) 19.9,78.825 20.375,79.3 20.375,82.5 v2(20.175,82.7)
  Bottom Layer w0.483: v2(13.975,78.825) 13.975,77 13.975,76.625 13.975,74.525 14.297,74.203 U12.1@14.5,74.203 ; v2(20.175,82.7) D5.1@21.4,82.7
NetD6_1: D6.1 R83.2 | length 1.6
  Bottom Layer w0.25: R83.2@41.3,17.64 D6.1@41.3,19.2
NetD7_1: D7.1 R86.2 | length 2.6
  Bottom Layer w0.25: D7.1@37.9,3.1 R86.2@40.49,3.1
NetD8_1: D8.1 R84.2 | length 3.3
  Bottom Layer w0.25: R84.2@9.61,30.76 D8.1@12.96,30.76
NetD9_1: D9.1 R85.2 | length 1.6
  Bottom Layer w0.25: D9.1@8.87,14.83 R85.2@8.87,16.41 ; D9.1@9.49,14.81 D9.1@9.5,14.8
NetD10_1: D10.1 R17.1 | length 8
  Top Layer w0.25: v1(10.75,9.375) 10.76,9.365 v1@10.76,7.32
  Bottom Layer w0.25: R17.1@7.225,9.375 v1(10.75,9.375) ; v1(10.79,7.3) 11.26,6.83 D10.1@12.97,6.83 ; D10.1@12.99,6.81 D10.1@13,6.8
NetD11_1: D11.1 R18.1 | length 4.8
  Top Layer w0.2: v1(41.59,7.6) v1(41.59,10.09)
  Bottom Layer w0.2: R18.1@40.52,7.6 v1(41.59,7.6) ; D11.1@41.3,11.2 41.59,10.91 v1(41.59,10.09)
NetD12_1: D12.1 R15.1 | length 5.4
  Top Layer w0.2: v1(10.46,24.01) 11.43,24.98 v1(11.43,26.28)
  Bottom Layer w0.2: D12.1@9,22.8 9.25,22.8 v1(10.46,24.01) ; D12.1@9.5,22.8 D12.1@9.58,22.8 ; R15.1@10.74,26.28 v1(11.43,26.28)
NetD13_1: D13.1 R78.1 | length 4.9
  Top Layer w0.25: v1(39.71,26.57) 39.71,24.82 v1(39.72,24.83)
  Bottom Layer w0.25: D13.1@37.8,27.2 39.32,27.2 39.71,26.81 v1(39.71,26.57) ; v1(39.72,24.83) R78.1@40.56,24.83
NetD14_1: D14.1 R87.1 | length 2.9
  Bottom Layer w0.25: R87.1@23.06,16.88 23.06,16.73 24.12,15.67 D14.1@25.4,15.67
NetJ2_12: J2.12 R77.1 | length 2.1
  Bottom Layer w0.229: R77.1@43.425,48.025 43.475,47.975 J2.12@45.475,47.975
NetJP3_1: JP3.1 R89.1 | length 60.6
  Top Layer w0.483: R89.1@5.1,40.975 5.125,41 v2(5.125,41.65)
  POW w0.483: v2(5.125,41.65) 5.125,76.35 6.275,77.5 23.325,77.5 24.954,79.129 24.954,81.17 26.425,82.641 JP3.1@26.425,82.77
NetJP6_2: JP6.2 R7.2 R8.2 R90.1 U3.1 | length 16
  Top Layer w0.305: v2(33.9,56.3) v2(35.5,56.3)
  Bottom Layer w0.305: R8.2@32.775,56.775 R90.1@33.875,56.775 R7.2@33.875,55.65
  Bottom Layer w0.381: v2(35.5,56.3) 42.85,56.3 43.945,55.205 43.945,55.025 JP6.2@43.945,54.775 43.945,53.345 43.6,53 U3.1@42.7,53
NetL9_1: L9.1 U6.5 | length 2
  Top Layer w0.483: U6.5@23.453,79.275 23.453,78.323 L9.1@24.225,77.55
NetQ1_1: Q1.1 R91.1 R92.2 U7.5 U13.5 | length 18
  Top Layer w0.25: U13.5@40.35,71.925 41.5,71.925 41.875,72.3 v1(41.875,72.5)
  Bottom Layer w0.25: Q1.1@37.298,77.688 Q1.1@37.298,77.666 ; v1(41.875,72.5) R92.2@40.05,72.5 39.461,73.089 39.461,75.939 38.85,76.55 38.413,76.55 Q1.1@37.298,77.666 ; U7.5@43.775,78.875 43.775,79.15 43.6,79.325 38.575,79.325 37.275,78.025 37.275,77.688 Q1.1@37.298,77.666
NetQ1_3: Q1.3 R95.1 | length 2.6
  Bottom Layer w0.25: R95.1@38.45,73.825 R95.1@38.675,73.6 ; Q1.3@38.45,75.147 Q1.3@38.263,75.334 38.263,74.012 R95.1@38.675,73.6 ; R95.1@38.675,73.553 R95.1@38.675,73.6 ; R95.1@38.725,73.55 R95.1@38.675,73.6
NetR11_2: R11.2 USB1.2 | length 8.7
  Top Layer w0.254: 8.1,71.825 8.1,71.953 ; USB1.2@8.1,74.675 8.1,71.953 ; R11.2@12.6,69.9 R11.2@12.55,69.9 12.275,69.9 11.325,70.85 8.425,70.85 8.1,71.175 8.1,71.953
NetR12_2: R12.2 U2.19 | length 16.5
  POW w0.25: v1(49,76.775) 49.325,76.775 49.675,76.425 49.675,69.9 v1(49.25,69.475)
  Bottom Layer w0.25: U2.19@45.05,65.125 48.4,65.125 49.2,65.925 49.2,69.425 v1(49.25,69.475) ; R12.2@48.475,76.775 v1(49,76.775)
NetR13_2: R13.2 U11.10 | length 1.9
  Bottom Layer w0.114: U11.10@18.825,48 R13.2@18.825,49.875
NetR19_2: R19.2 R21.1 R23.1 U4.3 | length 3.4
  Top Layer w0.25: U4.3@37.45,58.525 37.75,58.825 v1(38.577,58.825)
  Bottom Layer w0.25: R23.1@37.1,58.825 R21.1@38.175,58.825 v1(38.577,58.825) R19.2@39.275,58.825
NetR22_2: R22.2 R24.1 U2.30 | length 3.4
  Bottom Layer w0.25: R22.2@40.425,59.8 R24.1@41.525,59.8 41.9,60.175 U2.30@41.9,61.975
NetR26_2: R26.2 R29.2 U5.E14 | length 23.8
  Top Layer w0.114: U5.E14@20.35,67.175 v1(20.35,67.7) v1@20.35,67.775 ; v1(27.325,68.1) 27.95,68.1 29.65,66.4 36.15,66.4 36.775,65.775 v1@36.775,62.4 ; v1@36.65,62.425 v1@36.7,62.375
  POW w0.114: v1@20.325,67.775 v1@20.35,67.775 ; v1(20.35,67.7) 20.85,67.2 24.175,67.2 25.075,68.1 v1(27.325,68.1)
  Bottom Layer w0.114: v1@36.775,62.4 36.775,62.125 R29.2@37.025,61.875 R26.2@38.125,61.875
  other v1: 36.725,62.35
NetR27_1: R27.1 U5.F12 | length 1.3
  Top Layer w0.114: U5.F12@21.15,65.582 U5.F12@21.15,65.575 21.15,65.45 v1(21.4,65.2)
  Bottom Layer w0.114: v1(21.4,65.2) 21.4,65.775 R27.1@21.6,65.975
NetR27_2: R27.2 U5.G14 | length 1.3
  Top Layer w0.114: U5.G14@21.95,67.175 v1(21.95,67.65)
  Bottom Layer w0.114: R27.2@21.6,66.975 21.95,67.325 v1(21.95,67.65) v1@21.95,67.7
NetR28_2: R28.2 U5.D12 | length 8.4
  Top Layer w0.114: R28.2@13.55,64.275 14.45,65.175 17.101,65.175 ; 15.275,65.175 17.101,65.175 ; U5.D12@19.55,65.575 19.15,65.175 17.101,65.175
NetR37_1: R37.1 U5.B1 | length 9.7
  Top Layer w0.114: U5.B1@17.95,56.775 17.95,56.303 20.22,54.033 23.867,54.033 24.075,53.825 24.4,53.825 v1(24.475,53.9)
  Bottom Layer w0.114: v1(24.475,53.9) R37.1@24.475,55.5
NetR41_1: R41.1 R42.2 U5.C13 | length 7.2
  Top Layer w0.114: v1(15.225,67.275) 15.5,67.275 16.165,67.94 17.101,67.94 18.546,67.94 19.146,67.339 19.146,66.771 U5.C13@18.75,66.375
  Bottom Layer w0.114: R41.1@14.7,66.15 R42.2@14.7,67.25 v1@15.225,67.25
NetR45_1: R45.1 U5.A12 | length 4.2
  Top Layer w0.127: R45.1@13.55,65.4 13.725,65.575 15.626,65.575 ; 15.05,65.575 15.626,65.575 ; U5.A12@17.15,65.575 15.626,65.575
NetR46_1: R46.1 U5.B12 | length 5.5
  Top Layer w0.114: R46.1@13.55,66.525 14.1,65.975 15.751,65.975 ; 15.025,65.975 15.751,65.975 ; U5.B12@17.95,65.575 17.55,65.975 15.751,65.975
NetR47_1: R47.1 U5.B13 | length 4.9
  Top Layer w0.114: R47.1@13.55,67.65 13.675,67.65 14.55,66.775 17.55,66.775 U5.B13@17.95,66.375
NetR48_2: R48.2 USB1.3 | length 9.7
  Top Layer w0.254: USB1.3@7.3,74.675 7.3,71.225 8.125,70.4 10.7,70.4 11.138,69.962 12.325,68.775 R48.2@12.55,68.775
NetR51_1: R51.1 R52.2 U1.7 | length 3.6
  Bottom Layer w0.25: U1.7@28.96,46.819 28.96,47.485 29.9,48.425 29.9,48.925 R52.2@29.9,50
NetR64_1: R64.1 U10.7 | length 6.7
  Bottom Layer w0.114: U10.7@32.475,44.31 31.972,44.31 31.607,44.675 31.607,47.857 32.1,48.35 33.05,48.35 33.45,48.75 R64.1@33.45,49.075
NetR73_2: R73.2 R75.2 U10.3 | length 7.9
  Bottom Layer w0.114: R73.2@38.325,49.125 39.475,49.125 39.5,49.125 40.15,48.475 40.15,44 U10.3@39.19,43.04
NetR94_1: R94.1 U7.8 | length 16.4
  Bottom Layer w0.25: R94.1@37.55,73.55 37.35,73.75 37.35,75.25 36.3,76.3 36.3,78.6 36.988,79.288 37.713,79.288 38.225,79.8 42.9,79.8 43.325,80.225 45.025,80.225 45.275,79.975 U7.8@45.275,78.875
NetU7_6: U7.6 U7.15 U13.1 | length 10
  Top Layer w0.25: U13.1@40.35,79.675 v1(44.25,79.675)
  POW w0.25: v1(44.25,79.675) 44.275,79.65 v1(44.275,75.1)
  Bottom Layer w0.25: v1(44.275,75.1) U7.15@44.275,75.875 ; U7.6@44.275,78.875 v1@44.275,79.65
NetU7_7: U7.7 U7.14 U13.2 | length 9.8
  Top Layer w0.25: v1(44.775,79.675) U13.2@48.25,79.675
  POW w0.25: v1(44.775,75.1) v1(44.775,79.675)
  Bottom Layer w0.25: v1(44.775,75.1) U7.14@44.775,75.875 ; U7.7@44.775,78.725 U7.7@44.775,78.875 v1@44.775,79.65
